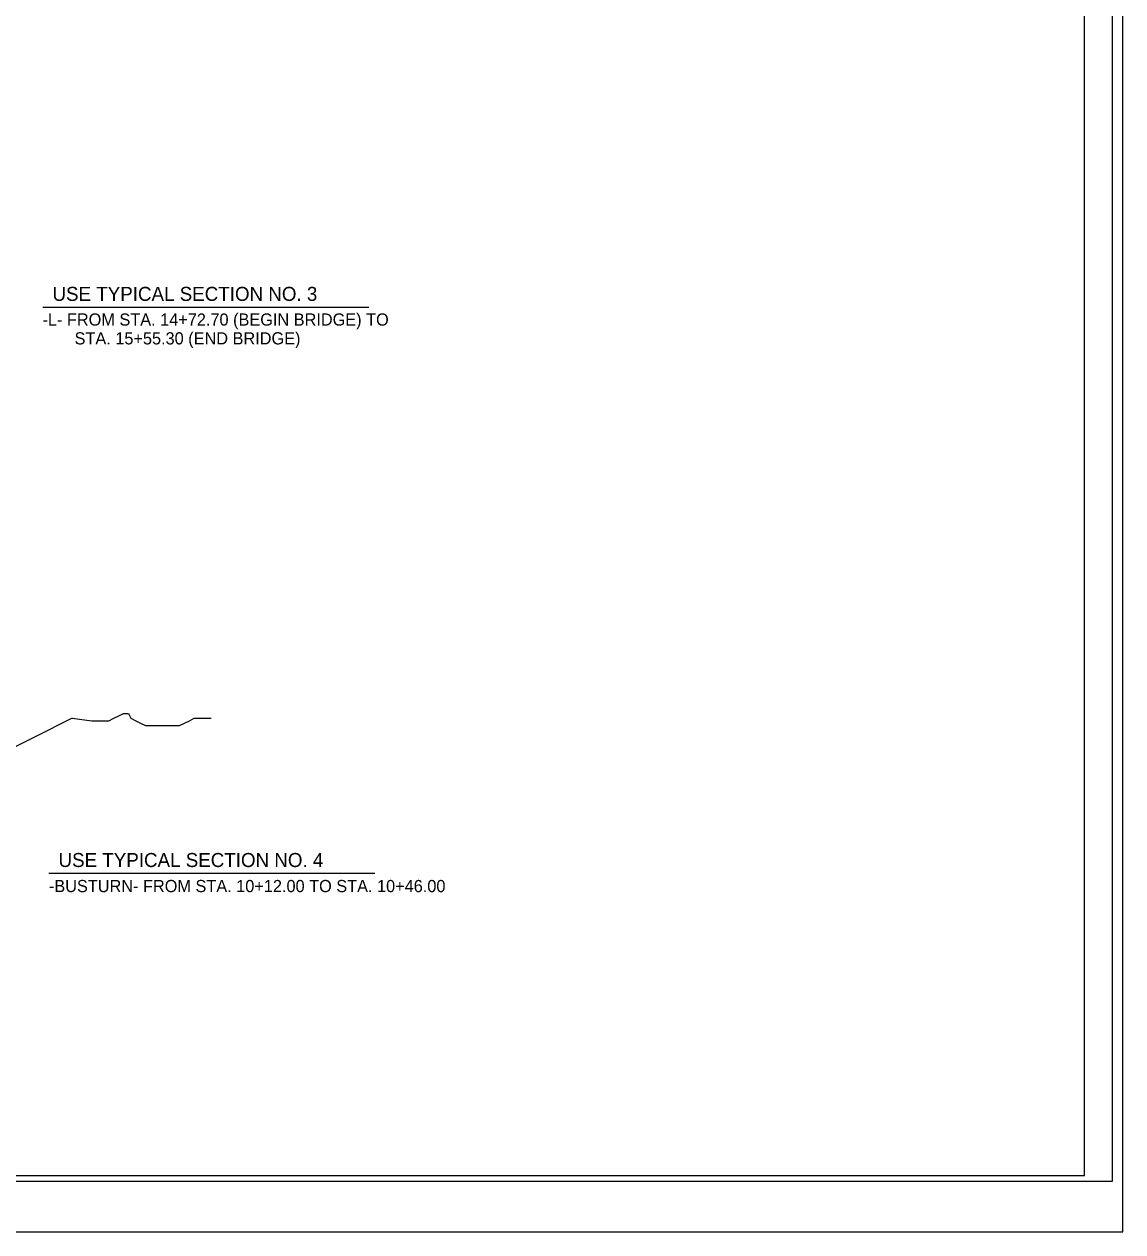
# Model space of a CAD drawing. Extents: x 573771 to 574316, y -53454 to -53190.
# Drawn here: x 574199.3 to 574316.1, y -53453.5 to -53325.1 of the extents above; entities that cross this region are included whole.
import ezdxf

# ---------------------------------------------------------------- set-up
doc = ezdxf.new("R2010")
doc.units = 0
for name, color, linetype in [('Sheet Cutting Line CELL', 7, 'Continuous'), ('Sheet Plot Border Inside CELL', 7, 'Continuous'), ('Sheet Plot Border Outside CELL', 7, 'Continuous'), ('Sheet Typical CELL', 7, 'Continuous'), ('Typical Pavement Slope Information CELL', 7, 'Continuous'), ('Typical Slope Point Local CELL', 7, 'Continuous'), ('Typical Text Label CELL', 7, 'Continuous')]:
    doc.layers.add(name, color=color, linetype=linetype)

msp = doc.modelspace()

# ---------------------------------------------------------------- linework, layer by layer
at = {"layer": 'Sheet Cutting Line CELL'}
msp.add_line((573911.95, -53453.54), (574316.11, -53453.54), dxfattribs=at)
at = {"layer": 'Sheet Plot Border Inside CELL'}
msp.add_lwpolyline([(574315.03, -53194.93), (573915.07, -53194.93), (573915.07, -53448.15), (574315.03, -53448.15)], close=True, dxfattribs=at)
at = {"layer": 'Sheet Plot Border Outside CELL'}
msp.add_lwpolyline([(574316.11, -53189.54), (573911.95, -53189.54), (573911.95, -53453.54), (574316.11, -53453.54)], close=True, dxfattribs=at)
at = {"layer": 'Sheet Typical CELL'}
msp.add_lwpolyline([(574312.03, -53195.54), (573952.03, -53195.54), (573952.03, -53447.54), (574312.03, -53447.54)], close=True, dxfattribs=at)
at = {"layer": 'Typical Slope Point Local CELL'}
msp.add_line((574204.42, -53398.93), (574188.51, -53406.89), dxfattribs=at)
msp.add_lwpolyline([(574204.42, -53398.93), (574206.49, -53399.19), (574207.01, -53399.19), (574207.79, -53399.19), (574208.31, -53399.19), (574208.83, -53398.93), (574209.35, -53398.67), (574209.86, -53398.41), (574210.38, -53398.41), (574210.64, -53398.93), (574211.16, -53399.19), (574211.68, -53399.45), (574212.2, -53399.71), (574212.72, -53399.71), (574213.24, -53399.71), (574213.76, -53399.71), (574214.27, -53399.71), (574214.79, -53399.71), (574215.31, -53399.71), (574215.83, -53399.71), (574216.35, -53399.45), (574216.87, -53399.19), (574217.39, -53398.93), (574218.16, -53398.93), (574218.68, -53398.93), (574219.2, -53398.93)], dxfattribs=at)
at = {"layer": 'Typical Text Label CELL'}
for p, q in [((574201.28, -53355.23), (574235.93, -53355.23)), ((574201.93, -53415.42), (574236.57, -53415.42))]:
    msp.add_line(p, q, dxfattribs=at)

# ---------------------------------------------------------------- texts
at = {"layer": 'Typical Pavement Slope Information CELL'}
for s, p in [('-L- FROM STA. 14+72.70 (BEGIN BRIDGE) TO ', (574201.25, -53357.18)), ('STA. 15+55.30 (END BRIDGE)', (574204.66, -53359.18)), ('-BUSTURN- FROM STA. 10+12.00 TO STA. 10+46.00', (574201.93, -53417.42))]:
    msp.add_text(s, height=1.2952, dxfattribs=at).set_placement(p)
at = {"layer": 'Typical Text Label CELL'}
for s, p in [('USE TYPICAL SECTION NO. 3', (574202.31, -53354.55)), ('USE TYPICAL SECTION NO. 4', (574202.95, -53414.75))]:
    msp.add_text(s, height=1.4919, dxfattribs=at).set_placement(p)

doc.saveas('drawing.dxf')
